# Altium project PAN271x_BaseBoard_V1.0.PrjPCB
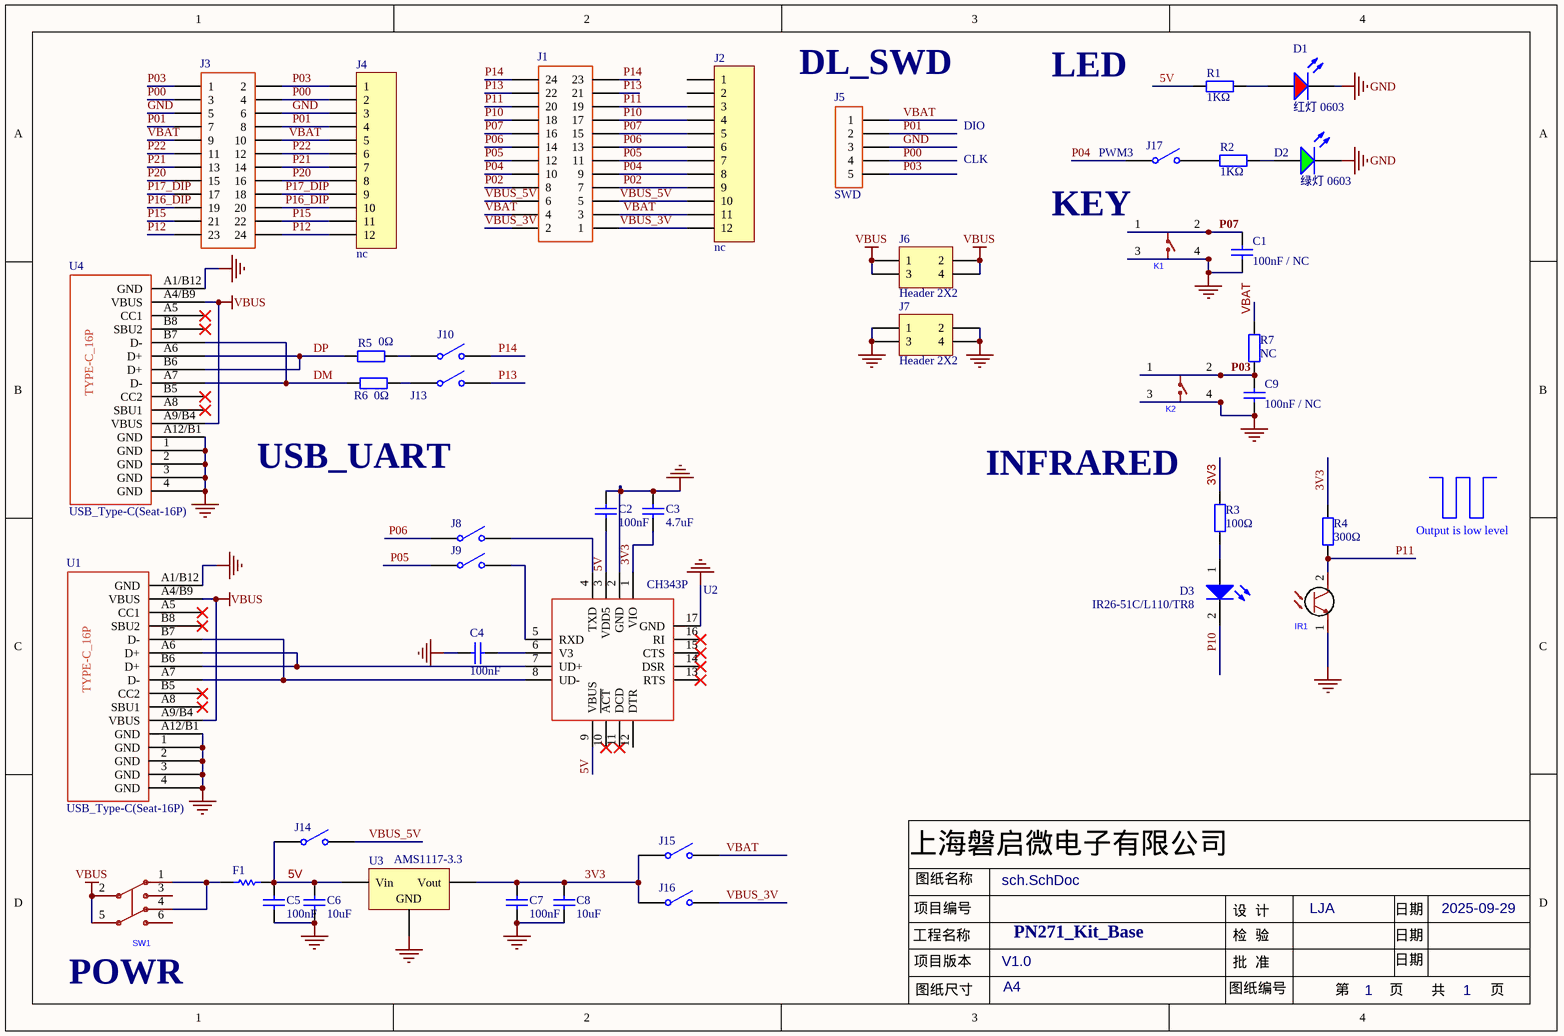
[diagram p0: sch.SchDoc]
1 sheet, 43 parts. Net scope: hierarchical (ports join the sheet entries above them; power ports are global).
Board file: pcb.PcbDoc

## Sheet sch.SchDoc: PAN271_Kit_Base
size A4; Date: 2025-09-29; Author: LJA; CompanyName: 上海磐启微电子有限公司; DrawnBy: 4; Engineer: 5; Organization: 6; Address1: 7; Address2: 8; Address3: 9; Address4: 10; DocumentNumber: 1; Revision: V1.0; SheetNumber: 1; SheetTotal: 1; VersionControl_RevNumber: 17; IsUserConfigurable: 16; VersionControl_ProjFolderRevNumber: 15; Parameter 1: 12

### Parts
C1  100nF / NC  [0402_C]
C2  100nF  [0402_C]
C3  4.7uF  [0402_C]
C4  100nF  [0402_C]
C5  100nF  [0402_C]
C6  10uF  [0402_C]
C7  100nF  [0402_C]
C8  10uF  [0402_C]
C9  100nF / NC  [0402_C]
D1  红灯 0603  [0603_LED_S1]
D2  绿灯 0603  [0603_LED_S1]
D3  IR26-51C/L110/TR8  [FP-IR26-51C-L110-TR8-MFG]
F1  (no value)  [0603_R]
IR1  PT26-51B/TR8  [OPTO-SMD_PT26-51B-TR8]  (value not drawn)
J1  Header 2x12  [Header 2X12]  (value not drawn)
J2  nc  [HDR1X12]
J3  Header 2x12  [Header 2X12]  (value not drawn)
J4  nc  [HDR1X12]
J5  SWD  [XH 1x5]
J6  Header 2X2  [HDR2X2]
J7  Header 2X2  [HDR2X2]
J8  Header 2  [Header 1x2]  (value not drawn)
J9  Header 2  [Header 1x2]  (value not drawn)
J10  Header 2  [Header 1x2]  (value not drawn)
J13  Header 2  [Header 1x2]  (value not drawn)
J14  Header 2  [Header 1x2]  (value not drawn)
J15  Header 2  [Header 1x2]  (value not drawn)
J16  Header 2  [Header 1x2]  (value not drawn)
J17  Header 2  [Header 1x2]  (value not drawn)
K1  K2-1808GN-A4SW-04  [KEY-SMD_4P-L4.2-W3.2-P2.20-LS5.1-TL]  (value not drawn)
K2  K2-1808GN-A4SW-04  [KEY-SMD_4P-L4.2-W3.2-P2.20-LS5.1-TL]  (value not drawn)
R1  1KΩ  [0402_R]
R2  1KΩ  [0402_R]
R3  100Ω  [0402_R]
R4  300Ω  [0402_R]
R5  0Ω  [0402_R]
R6  0Ω  [0402_R]
R7  NC  [0402_R]
SW1  K8-5851E-L1  [SW-TH_6P-L5.8-W5.8-P2.00-LS4.5-TL_K8-5851E-L1]  (value not drawn)
U1  USB_Type-C(Seat-16P)  [USB-C-SMD_TYPE-C16PIN]
U2  CH343P  [QFN16]
U3  AMS1117-3.3  [SOT-223]
U4  USB_Type-C(Seat-16P)  [USB-C-SMD_TYPE-C16PIN]

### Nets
GND: C1.1 C2.2 C3.2 C4.2 C5.1 C6.1 C7.1 C8.1 C9.1 D1.K D2.K IR1.1 J3.5 J3.6 J4.3 J5.3 J7.1 J7.2 J7.3 J7.4 K1.3 K1.4 K2.3 K2.4 U1.1(GND) U1.2(GND) U1.3(GND) U1.4(GND) U1.A1/B12(GND) U1.A12/B1(GND) U2.2(GND) U2.17(GND) U3.1(GND) U4.1(GND) U4.2(GND) U4.3(GND) U4.4(GND) U4.A1/B12(GND) U4.A12/B1(GND)
VBUS: J6.1 J6.2 J6.3 J6.4 SW1.2 SW1.5 U1.A4/B9(VBUS) U1.A9/B4(VBUS) U4.A4/B9(VBUS) U4.A9/B4(VBUS)
3V3: C3.1 C7.2 C8.2 J15.1(COMMON) J16.1(COMMON) R3.2 R4.2 U2.1(VIO) U3.2(Vout)  [project net 3V3_1]
5V: C2.1 C5.2 C6.2 F1.2 J14.1(COMMON) R1.1 U2.3(VDD5) U2.9(VBUS) U3.3(Vin)  [project net 5V_1]
DM: R6.2 U4.A7(D-) U4.B7(D-)  [project net DM_1]
DP: R5.2 U4.A6(D+) U4.B6(D+)  [project net DP_1]
P00: J3.3 J3.4 J4.2 J5.4  [project net P00_1]
P01: J3.7 J3.8 J4.4 J5.2  [project net P01_1]
P02: J1.7 J1.8 J2.9  [project net P02_1]
P03: C9.2 J3.1 J3.2 J4.1 J5.5 K2.1 K2.2 R7.1  [project net P03_1]
P04: J1.9 J1.10 J2.8 J17.1(COMMON)  [project net P04_1]
P05: J1.11 J1.12 J2.7 J9.1(COMMON)  [project net P05_1]
P06: J1.13 J1.14 J2.6 J8.1(COMMON)  [project net P06_1]
P07: C1.2 J1.15 J1.16 J2.5 K1.1 K1.2  [project net P07_1]
P10: D3.2(C) J1.17 J1.18 J2.4  [project net P10_1]
P11: IR1.2 J1.19 J1.20 J2.3 R4.1  [project net P11_1]
P12: J3.23 J3.24 J4.12  [project net P12_1]
P13: J1.21 J1.22 J13.2(NO)  [project net P13_1]
P14: J1.23 J1.24 J10.2(NO)  [project net P14_1]
P15: J3.21 J3.22 J4.11  [project net P15_1]
P16_DIP: J3.19 J3.20 J4.10  [project net P16_DIP_1]
P17_DIP: J3.17 J3.18 J4.9  [project net P17_DIP_1]
P20: J3.15 J3.16 J4.8  [project net P20_1]
P21: J3.13 J3.14 J4.7  [project net P21_1]
P22: J3.11 J3.12 J4.6  [project net P22_1]
VBAT: J1.3 J1.4 J2.11 J3.9 J3.10 J4.5 J5.1 J15.2(NO) R7.2  [project net VBAT_1]
VBUS_3V: J1.1 J1.2 J2.12 J16.2(NO)  [project net VBUS_3V_1]
VBUS_5V: J1.5 J1.6 J2.10 J14.2(NO)  [project net VBUS_5V_1]
NetC4_1: C4.1 U2.6(V3)
NetD1_A: D1.A R1.2
NetD2_A: D2.A R2.2
NetD3_1: D3.1(A) R3.1
NetF1_1: F1.1 SW1.1 SW1.4
NetJ8_2: J8.2(NO) U2.4(TXD)
NetJ9_2: J9.2(NO) U2.5(RXD)
NetJ10_1: J10.1(COMMON) R5.1
NetJ13_1: J13.1(COMMON) R6.1
NetJ17_2: J17.2(NO) R2.1
NetU1_A6: U1.A6(D+) U1.B6(D+) U2.7(UD+)
NetU1_A7: U1.A7(D-) U1.B7(D-) U2.8(UD-)

Not connected (* = marked no-connect by the designer): J2 1 2; SW1 3 6; U1 A5(CC1)* A8(SBU1)* B5(CC2)* B8(SBU2)*; U2 10(~{ACT})* 11(DCD)* 12(DTR) 13(RTS)* 14(DSR)* 15(CTS)* 16(RI)*; U4 A5(CC1)* A8(SBU1)* B5(CC2)* B8(SBU2)*

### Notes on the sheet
- (near J5) DL_SWD
- LED
- DIO
- CLK
- (near J17) PWM3
- KEY
- USB_UART
- INFRARED
- Output is low level
- (near SW1) POWR
- PN271_Kit_Base

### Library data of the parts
C1 C2 C4 C5 C7 C9 = 0402 100nF (104) 10% 16V: 贴片电容
C3 = 0402 4.7uF (475) 20% 10V: 贴片电容
C6 C8 = 0402 10uF (106) 20% 6.3V: 贴片电容
D1 = 0603 红灯: 发光二极管
D2 = 0603 绿灯: 发光二极管
D3 = IR26-51C/L110/TR8: EMITTER IR 940NM 65MA SMD; Viewing Angle: 20°; Number of LEDs: 1; Power Rating: 130mW; Forward Voltage: 1.2V; Lens Style: Diffused
F1 = Res1: Resistor
IR1 = PT26-51B/TR8: Manufacturer: EVERLIGHT(亿光); Add into BOM: yes; Collector - Emitter Voltage VCEO: 30V; Current - Collector(Ic): 20mA; Dissipation Power(Max): 75mW; Current - Dark(Id): 100nA; Peak Wavelength: 940nm; Vce Saturation(VCE(sat)): 0.4V@5mA
J1 J3 = Header 2x12: Header 2x11,2.54mm
J2 J4 = Header 12: Header, 12-Pin
J5 = Header 1x5: Header 1x5,2.54mm
J6 J7 = Header 2X2: Header, 2-Pin, Dual row
J8-J10 J13-J17 = SW-SPST: Header, 2-Pin
K1 K2 = K2-1808GN-A4SW-04: Manufacturer: 韩国韩荣; Add into BOM: yes; Circuit: 单刀单掷; Actuator Style: 椭圆形按钮; Operating Force: 250gf; Switch Length: 4.2mm; Switch Width: 3.25mm; Switch Height: 2.5mm; Contact Current: 50mA; Voltage Rating (DC): 12V; Insulation Resistance: 100MΩ; Mechanical Life: 10万次
R1 R2 R7 = 0402 1KΩ (1001) 1%: 贴片电阻
R3 R4 = 0402 300Ω (3000) 1%: 贴片电阻
R5 R6 = 0402 0Ω (0R0) 1%: 贴片电阻
SW1 = K8-5851E-L1: Manufacturer: 韩国韩荣; Add into BOM: yes; Self Lock / No Lock: 自锁; Actuator Style: 矩形按钮; Contact Current: 100mA; Voltage Rating: 30V; Actuator/Cap Color: 白色; With Lamp: 不带; Operating Force: 1.8N; Life: 10万次
U2 = CH343P: USB 转高速串口芯片
U3 = SOT-223 AMS1117-3.3: 低压差线性稳压(LDO)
